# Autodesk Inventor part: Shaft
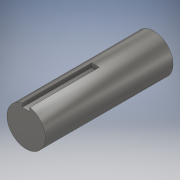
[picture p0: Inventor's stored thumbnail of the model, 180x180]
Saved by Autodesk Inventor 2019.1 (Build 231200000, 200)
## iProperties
Created: 2020-03
Part Number: Shaft
Material: Stainless Steel, 440C
Document SubType Name: Modeling
Designer: Oghenemarho
Density: 7.75 g/cm^3
Appearance: Semi-Polished
Author: Oghenemarho
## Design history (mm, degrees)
sketch "Sketch1"
  geometry: C1 r 15.24 at (0, 0); 1 further point
  constraints: 1 centre point, 1 coincident
  dimensions: "d0" = 30.48 diameter of C1
extrude "Extrusion1" new body sketch "Sketch1" distance "d1" = 101.6; taper "d2" = 0 deg
sketch "Sketch2"
  geometry: L1 (-2.997, 14.942)-(-2.997, 11.945); L2 (-2.997, 11.945)-(2.997, 11.945); L3 (2.997, 11.945)-(2.997, 14.942); A1 r 15.24 centre (0, 0) between (-2.997, 14.942) and (2.997, 14.942) reference; 1 further point
  constraints: 6 end point, 2 perpendicular, 2 point on circle, 1 parallel, 1 vertical
  dimensions: "d3" = 2.9972 distance of L1.start L1.end; "d4" = 5.9944 distance of L1.end L2.end
extrude "Extrusion2" cut sketch "Sketch2" distance "d5" = 54.991; taper "d6" = 0 deg
body "Solid1"
